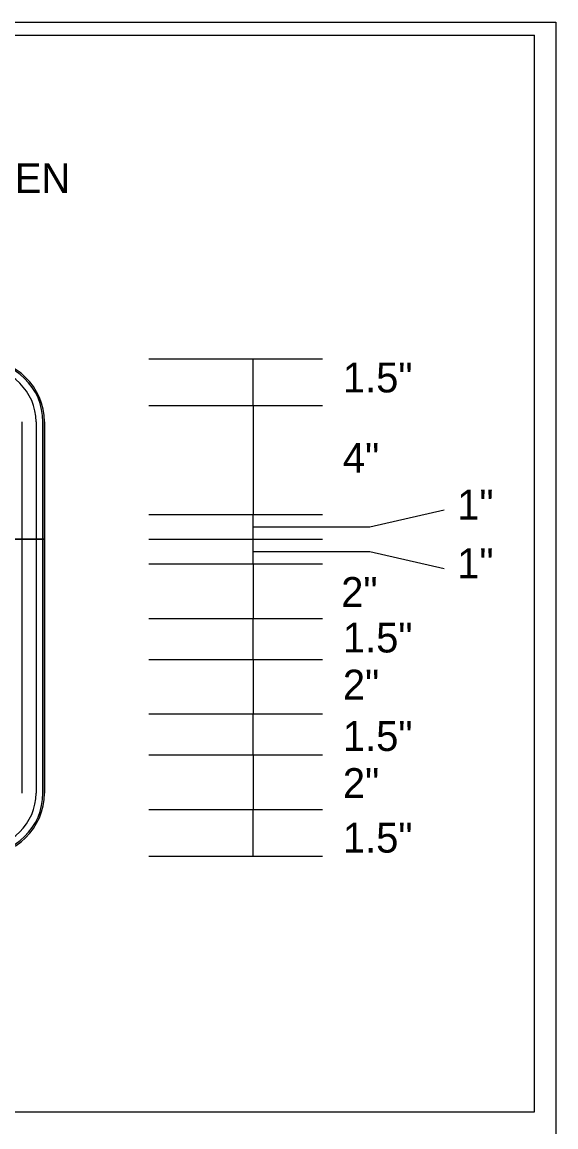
# Model space of a CAD drawing. Extents: x 53068 to 53703, y 9291 to 9710.
# Drawn here: x 53340.1 to 53391.3, y 9413.5 to 9519.5 of the extents above; entities that cross this region are included whole.
import ezdxf

# ---------------------------------------------------------------- set-up
doc = ezdxf.new("R2010")
doc.units = 0
for name, color, linetype in [('GSDims', 7, 'Continuous'), ('SheetLines_dp', 7, 'Continuous'), ('SignPanel', 7, 'Continuous'), ('SumBoxLinesMin_dp', 7, 'Continuous')]:
    doc.layers.add(name, color=color, linetype=linetype)

msp = doc.modelspace()

# ---------------------------------------------------------------- linework, layer by layer
at = {"layer": 'GSDims'}
for p, q in [((53352.25, 9487.17), (53368.95, 9487.17)), ((53362.27, 9482.72), (53362.27, 9487.17)), ((53352.25, 9482.72), (53368.95, 9482.72)), ((53352.25, 9482.72), (53368.95, 9482.72)), ((53362.27, 9482.72), (53362.27, 9472.23)), ((53373.47, 9471.05), (53380.61, 9472.69)), ((53352.25, 9472.23), (53368.95, 9472.23)), ((53352.25, 9472.23), (53368.95, 9472.23)), ((53362.27, 9469.87), (53362.27, 9472.23)), ((53362.27, 9471.05), (53373.47, 9471.05)), ((53352.25, 9469.87), (53368.95, 9469.87)), ((53352.25, 9469.87), (53368.95, 9469.87)), ((53362.27, 9467.51), (53362.27, 9469.87)), ((53362.27, 9468.69), (53373.47, 9468.69)), ((53373.47, 9468.69), (53380.61, 9467.05)), ((53352.25, 9467.51), (53368.95, 9467.51)), ((53352.25, 9467.51), (53368.95, 9467.51)), ((53362.27, 9467.51), (53362.27, 9462.27)), ((53352.25, 9462.27), (53368.95, 9462.27)), ((53352.25, 9462.27), (53368.95, 9462.27)), ((53362.27, 9458.34), (53362.27, 9462.27)), ((53352.25, 9458.34), (53368.95, 9458.34)), ((53352.25, 9458.34), (53368.95, 9458.34)), ((53362.27, 9458.34), (53362.27, 9453.1)), ((53352.25, 9453.1), (53368.95, 9453.1)), ((53352.25, 9453.1), (53368.95, 9453.1)), ((53362.27, 9449.16), (53362.27, 9453.1)), ((53352.25, 9449.16), (53368.95, 9449.16)), ((53352.25, 9449.16), (53368.95, 9449.16)), ((53362.27, 9449.16), (53362.27, 9443.92)), ((53352.25, 9443.92), (53368.95, 9443.92)), ((53352.25, 9443.92), (53368.95, 9443.92)), ((53362.27, 9439.46), (53362.27, 9443.92)), ((53352.25, 9439.46), (53368.95, 9439.46))]:
    msp.add_line(p, q, dxfattribs=at)
at = {"layer": 'SheetLines_dp'}
for p, q in [((53089.8, 9519.5), (53391.35, 9519.5)), ((53391.35, 9519.5), (53391.35, 9335.4))]:
    msp.add_line(p, q, dxfattribs=at)
at = {"layer": 'SignPanel'}
for p, q in [((53340.09, 9471.18), (53340.09, 9481.14)), ((53341.43, 9481.14), (53341.43, 9469.87)), ((53342.09, 9470), (53342.09, 9481.14)), ((53342.23, 9469.87), (53342.23, 9481.14)), ((53342.23, 9469.87), (53342.23, 9481.14)), ((53342.23, 9469.87), (53342.23, 9481.14)), ((53342.23, 9481.14), (53342.23, 9469.87)), ((53340.09, 9469.87), (53340.09, 9471.18)), ((53245.75, 9469.87), (53342.23, 9469.87)), ((53245.75, 9469.87), (53342.23, 9469.87)), ((53245.75, 9469.87), (53342.23, 9469.87)), ((53342.23, 9469.87), (53245.75, 9469.87)), ((53342.23, 9469.87), (53245.75, 9469.87)), ((53342.23, 9469.87), (53245.75, 9469.87)), ((53340.09, 9468.56), (53340.09, 9469.87)), ((53340.09, 9469.87), (53341.43, 9469.87)), ((53340.09, 9468.56), (53340.09, 9469.87)), ((53340.09, 9469.87), (53341.43, 9469.87)), ((53340.09, 9468.56), (53340.09, 9469.87)), ((53340.09, 9469.87), (53341.43, 9469.87)), ((53341.43, 9469.87), (53340.09, 9469.87)), ((53341.43, 9469.87), (53341.43, 9445.49)), ((53341.43, 9469.87), (53341.43, 9445.49)), ((53341.43, 9469.87), (53341.43, 9445.49)), ((53342.09, 9469.87), (53342.09, 9470)), ((53342.23, 9469.87), (53342.09, 9469.87)), ((53342.09, 9469.74), (53342.09, 9469.87)), ((53342.09, 9469.87), (53342.23, 9469.87)), ((53342.09, 9445.49), (53342.09, 9469.74)), ((53342.23, 9445.49), (53342.23, 9469.87)), ((53342.23, 9445.49), (53342.23, 9469.87)), ((53342.23, 9445.49), (53342.23, 9469.87)), ((53342.23, 9469.87), (53342.23, 9445.49)), ((53340.09, 9445.49), (53340.09, 9468.56)), ((53340.09, 9445.49), (53340.09, 9468.56)), ((53340.09, 9445.49), (53340.09, 9468.56))]:
    msp.add_line(p, q, dxfattribs=at)
for centre, major_axis, start_param, end_param in [((53336.08, 9481.14), (6.15, 0), 0, 1.570796), ((53336.08, 9481.14), (6.15, 0), 0, 1.570796), ((53336.08, 9481.14), (6.15, 0), 0, 1.570796), ((53336.08, 9481.14), (6.15, 0), 0, 1.570796), ((53336.08, 9481.14), (6.01, 0), 0, 1.570796), ((53336.08, 9481.14), (5.35, 0), 0, 1.570796), ((53336.08, 9445.49), (6.15, 0), 4.712389, 6.283185), ((53336.08, 9445.49), (5.35, 0), 4.712389, 6.283185), ((53336.08, 9445.49), (5.35, 0), 4.712389, 6.283185), ((53336.08, 9445.49), (5.35, 0), 4.712389, 6.283185), ((53336.08, 9445.49), (6.15, 0), 4.712389, 6.283185), ((53336.08, 9445.49), (6.15, 0), 4.712389, 6.283185), ((53336.08, 9445.49), (6.15, 0), 4.712389, 6.283185), ((53336.08, 9445.49), (6.01, 0), 4.712389, 6.283185)]:
    msp.add_ellipse(centre, major_axis=major_axis, ratio=0.980782, start_param=start_param, end_param=end_param, dxfattribs=at)
at = {"layer": 'SumBoxLinesMin_dp'}
for p, q in [((53092.7, 9518.25), (53389.3, 9518.25)), ((53389.3, 9414.91), (53389.3, 9518.25)), ((53092.7, 9414.91), (53389.3, 9414.91))]:
    msp.add_line(p, q, dxfattribs=at)

# ---------------------------------------------------------------- texts
at = {"layer": 'GSDims'}
for s, height, p in [('NO BLACK DIVISIONAL LINE BETWEEN', 2.8669, (53273.13, 9503.09)), ('1.5"', 2.867, (53370.89, 9483.96)), ('4"', 2.867, (53370.89, 9476.25)), ('1"', 2.867, (53381.87, 9471.76)), ('1"', 2.867, (53381.87, 9466.13)), ('2"', 2.867, (53370.73, 9463.37)), ('1.5"', 2.867, (53370.89, 9459)), ('2"', 2.867, (53370.89, 9454.48)), ('1.5"', 2.867, (53370.89, 9449.55)), ('2"', 2.867, (53370.89, 9445.03)), ('1.5"', 2.867, (53370.89, 9439.79))]:
    msp.add_text(s, height=height, dxfattribs=at).set_placement(p)

doc.saveas('drawing.dxf')
